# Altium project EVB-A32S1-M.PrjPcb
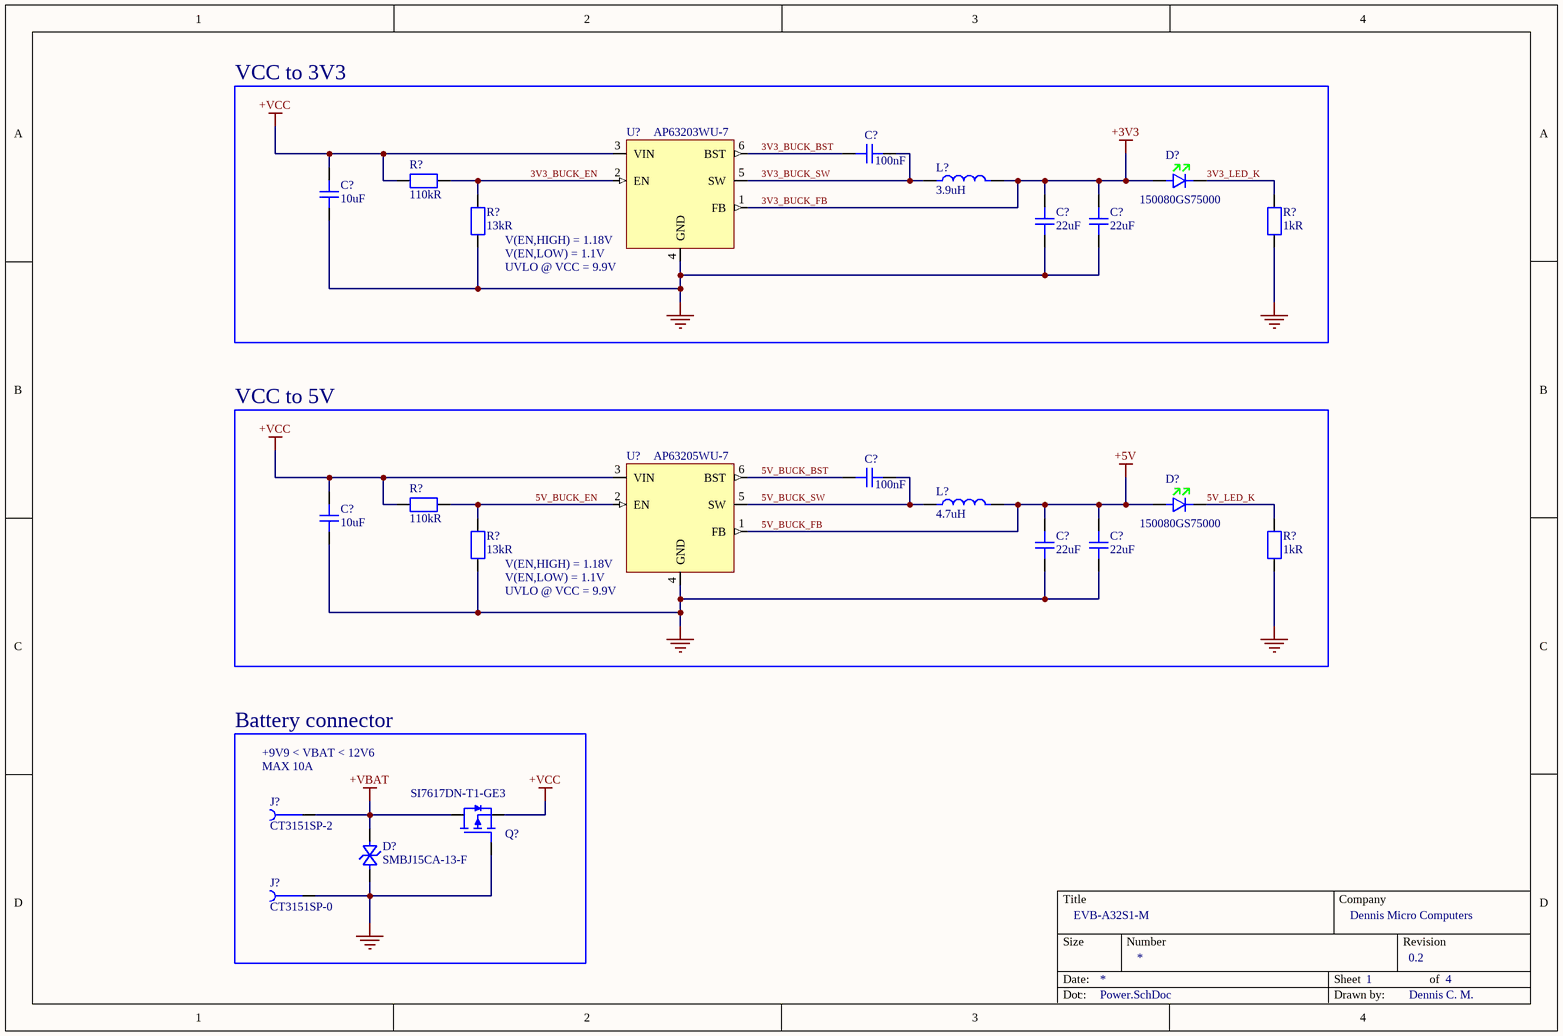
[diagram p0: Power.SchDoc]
Revision: 0.2; Title: EVB-A32S1-M; DrawnBy: Dennis C. M.; CompanyName: Dennis Micro Computers
4 sheets, 88 parts. Net scope: flat (ports and power ports of the same name join across sheets).
Sheets:
  Power.SchDoc
  MCU.SchDoc
  Motor.SchDoc
  Sensing.SchDoc

## Sheet Power.SchDoc: EVB-A32S1-M
size A4; SheetNumber: 1; SheetTotal: 4

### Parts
(Parts that share a designator on the sheet are numbered #1, #2 ... from top to bottom, then left to right.)
C?#1  value 100nF  [C_Yageo_CC_0402_A]  (hidden comment: CC0402MRX5R6BB104)
C?#2  value 10uF  [C_Yageo_CC_0805_A]  (hidden comment: CC0805KRX5R7BB106)
C?#3  value 22uF  [C_Yageo_CC_0805_A]  (hidden comment: CC0805MKX5R6BB226)
C?#4  value 22uF  [C_Yageo_CC_0805_A]  (hidden comment: CC0805MKX5R6BB226)
C?#5  value 100nF  [C_Yageo_CC_0402_A]  (hidden comment: CC0402MRX5R6BB104)
C?#6  value 10uF  [C_Yageo_CC_0805_A]  (hidden comment: CC0805KRX5R7BB106)
C?#7  value 22uF  [C_Yageo_CC_0805_A]  (hidden comment: CC0805MKX5R6BB226)
C?#8  value 22uF  [C_Yageo_CC_0805_A]  (hidden comment: CC0805MKX5R6BB226)
D?#1  150080GS75000  [D_LED_We_150080GS75000]
D?#2  150080GS75000  [D_LED_We_150080GS75000]
D?#3  SMBJ15CA-13-F  [D_TVS_BI_Diodes_SMBJ15CA-13-F_A]
J?#1  CT3151SP-2  [J_CalTest_CT3151SP-2]
J?#2  CT3151SP-0  [J_CalTest_CT3151SP-0]
L?#1  value 3.9uH  [L_Murata_1255AY-XXXX=P3]  (hidden comment: 1255AY-3R9N=P3)
L?#2  value 4.7uH  [L_Murata_1255AY-XXXX=P3]  (hidden comment: 1255AY-4R7M=P3)
Q?#1  SI7617DN-T1-GE3  [Q_Vishay_SI7617DN-T1-GE3]
R?#1  value 110kR  [R_Yageo_RCL_0402_A]  (hidden comment: RC0402FR-07110KL)
R?#2  value 13kR  [R_Yageo_RCL_0402_A]  (hidden comment: RC0402FR-0713KL)
R?#3  value 1kR  [R_Yageo_RCL_0402_A]  (hidden comment: RC0402FR-071KL)
R?#4  value 110kR  [R_Yageo_RCL_0402_A]  (hidden comment: RC0402FR-07110KL)
R?#5  value 13kR  [R_Yageo_RCL_0402_A]  (hidden comment: RC0402FR-0713KL)
R?#6  value 1kR  [R_Yageo_RCL_0402_A]  (hidden comment: RC0402FR-071KL)
U?#1  AP63203WU-7  [U_Diodes_AP623xx]
U?#2  AP63205WU-7  [U_Diodes_AP623xx]

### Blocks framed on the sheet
VCC to 3V3: C?#1-C?#4 D?#1 L?#1 R?#1-R?#3 U?#1
VCC to 5V: C?#5-C?#8 D?#2 L?#2 R?#4-R?#6 U?#2
Battery connector: D?#3 J?#1 J?#2 Q?#1

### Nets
3V3_BUCK_FB: C?#3.2 C?#4.2 D?#1.1 L?#1.2 U?#1.1(FB)  [also labelled +3V3]
5V_BUCK_FB: C?#7.2 C?#8.2 D?#2.1 L?#2.2 U?#2.1(FB)  [also labelled +5V]
+VBAT: D?#3.1 J?#1.1 Q?#1.1(D)
+VCC: C?#2.2 C?#6.2 Q?#1.3(S) R?#1.2 R?#4.2 U?#1.3(VIN) U?#2.3(VIN)
GND: C?#2.1 C?#3.1 C?#4.1 C?#6.1 C?#7.1 C?#8.1 D?#3.2 J?#2.1 Q?#1.2(G) R?#2.1 R?#3.1 R?#5.1 R?#6.1 U?#1.4(GND) U?#2.4(GND)
3V3_BUCK_BST: C?#1.2 U?#1.6(BST)
3V3_BUCK_EN: R?#1.1 R?#2.2 U?#1.2(EN)
3V3_BUCK_SW: C?#1.1 L?#1.1 U?#1.5(SW)
3V3_LED_K: D?#1.2 R?#3.2
5V_BUCK_BST: C?#5.2 U?#2.6(BST)
5V_BUCK_EN: R?#4.1 R?#5.2 U?#2.2(EN)
5V_BUCK_SW: C?#5.1 L?#2.1 U?#2.5(SW)
5V_LED_K: D?#2.2 R?#6.2

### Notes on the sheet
- (near U?#1) V(EN,HIGH) = 1.18V
- V(EN,LOW) = 1.1V
- (near U?#1) UVLO @ VCC = 9.9V
- (near U?#2) V(EN,HIGH) = 1.18V
- (near U?#2) UVLO @ VCC = 9.9V
- +9V9 < VBAT < 12V6
- (near J?#1) MAX 10A

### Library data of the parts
C?#1 C?#5 = CMP-001-00009-8: Multilayer Ceramic Capacitor, 0.1 uF, 25 V, ± 20%, X7R, 0402 [1005 Metric]; Dielectric: X5R; Temperature Coefficient: 30ppm/°C; Voltage Rating: 10V
C?#2 C?#6 = CMP-001-00018-3: 0805 10 uF 16 V ±10% Tolerance X5R Multilayer Ceramic Chip Capacitor; Voltage Rating (DC): 16V
C?#3 C?#4 C?#7 C?#8 = CMP-001-00014-5: Multilayer Ceramic Capacitor, 22 uF, 10 V, ± 20%, X5R, 0805 [2012 Metric]; Voltage Rating (DC): 10V
D?#1 D?#2 = CMP-007-00000-6: WURTH ELEKTRONIK - 150080GS75000 - LED, Green, SMD, 0805, 30 mA, 3.2 V, 520 nm; Forward Current: 30mA; Forward Voltage: 3.2V; Luminous Intensity: 450mcd; Max Reverse Voltage (DC): 5V; Lens Transparency: Clear; Power Dissipation: 105mW; Lens Style: Clear,Flat,Rectangular; Lens Size: 1.25mm; Viewing Angle: 140°; Test Current: 20mA; Dominant Wavelength: 520nm; Lens Color: Colorless
D?#3 = CMP-004-00000-8: Tvs Diode, Bidir, 15V, 600W, Do-214Aa Rohs Compliant: Yes; Max Reverse Leakage Current: 5uA; Reverse Breakdown Voltage: 16.7V; Breakdown Voltage: 19.2V; Clamping Voltage: 24.4V; Power Line Protection: No; Max Surge Current: 24A; Number of Bidirectional Channels: 1; Test Current: 1mA; Value: 280pF; Polarity: Bidirectional; Diode Type: ZENER
J?#1 = CMP-002-00001-9: Conn 4mm Safety Banana Jack F 1 POS Solder RA Thru-Hole 1 Port Bag; pin to pad: 1>1+2+3+4; Body Material: Nylon,Polyamide,PA66; Insulation: Mating End Insulated; Gender: Female
J?#2 = CMP-002-00000-11: Conn 4mm Safety Banana Jack F 1 POS Solder RA Thru-Hole 1 Port Bag; pin to pad: 1>1+2+3+4; Body Material: Nylon,Polyamide,PA66; Insulation: Mating End Insulated; Gender: Female
L?#1 = CMP-006-00002-2: Inductor Power Shielded Wirewound 3.9uH 30% 100KHz Ferrite 4.2A 0.0264Ohm DCR 2424 T/R; DC Resistance (DCR): 26.4mR; Saturation Current: 4.7A
L?#2 = CMP-006-00001-5: Inductor Power Shielded Wirewound 4.7uH 20% 100KHz Ferrite 4A 0.0276Ohm DCR 2424 T/R; DC Resistance (DCR): 27.6mR; Current Rating: 4.5A
Q?#1 = CMP-00000-6: P CHANNEL MOSFET, -30V, 35A; Transistor; Transistor Polarity: P Channel; Continuous Drain Current Id: -35A; Source; pin to pad: 1>5+6+7+8 2>4 3>1+2+3; Rise Time: 43ns; Drain to Source Resistance: 12.3mR; Turn-Off Delay Time: 30ns; Turn-On Delay Time: 40ns; Threshold Voltage: -2.5V; Max Power Dissipation: 52W; Fall Time: 11ns; Power Dissipation: 3.7W; Polarity: P-CHANNEL; Number of Elements: 1; Input Capacitance: 1.8nF; Gate to Source Voltage (Vgs): 25V
R?#1 R?#4 = CMP-009-00000-7: SMD Chip Resistor, 110 kOhm, ± 1%, 63 mW, 0402 [1005 Metric], Thick Film, General Purpose; Max Power Dissipation: 63mW; Voltage Rating (DC): 50V; Temperature Coefficient: 100ppm/°C
R?#2 R?#5 = CMP-009-00001-7: SMD Chip Resistor, 13 kOhm, ± 1%, 63 mW, 0402 [1005 Metric], Thick Film, General Purpose; Temperature Coefficient: 100ppm/°C; Voltage Rating: 50V; Max Power Dissipation: 63mW; Power Rating: 62.5mW
R?#3 R?#6 = CMP-009-00002-7: SMD Chip Resistor, 1 kOhm, ± 1%, 62.5 mW, 0402 [1005 Metric], Thick Film, General Purpose; Temperature Coefficient: 100ppm/°C; Voltage Rating (AC): 50V; Power Rating: 62.5mW; Max Power Dissipation: 63mW
U?#1 = CMP-019-00004-6: AP63203 Series 3.3 V 2 A SMT Fixed Low IQ Synchronous Buck - TSOT-26; Max Duty Cycle: 100%; Output Voltage: 3.3V; Number of Outputs: 1; Max Supply Voltage: 32V; Switching Frequency: 1.1MHz; Min Supply Voltage: 3.8V; Nominal Supply Current: 22uA; Output Current: 2A
U?#2 = CMP-019-00003-6: AP63205 Series 32 V 2 A 1.1 MHz Synchronous Buck Converter -TSOT-26; Number of Outputs: 1; Max Duty Cycle: 100%; Output Current: 2A; Switching Frequency: 1.1MHz; Max Supply Voltage: 32V; Output Voltage: 5V; Nominal Supply Current: 22uA; Min Supply Voltage: 3.8V

## Sheet MCU.SchDoc: EVB-A32S1-M
size A4; SheetNumber: 2; SheetTotal: 4
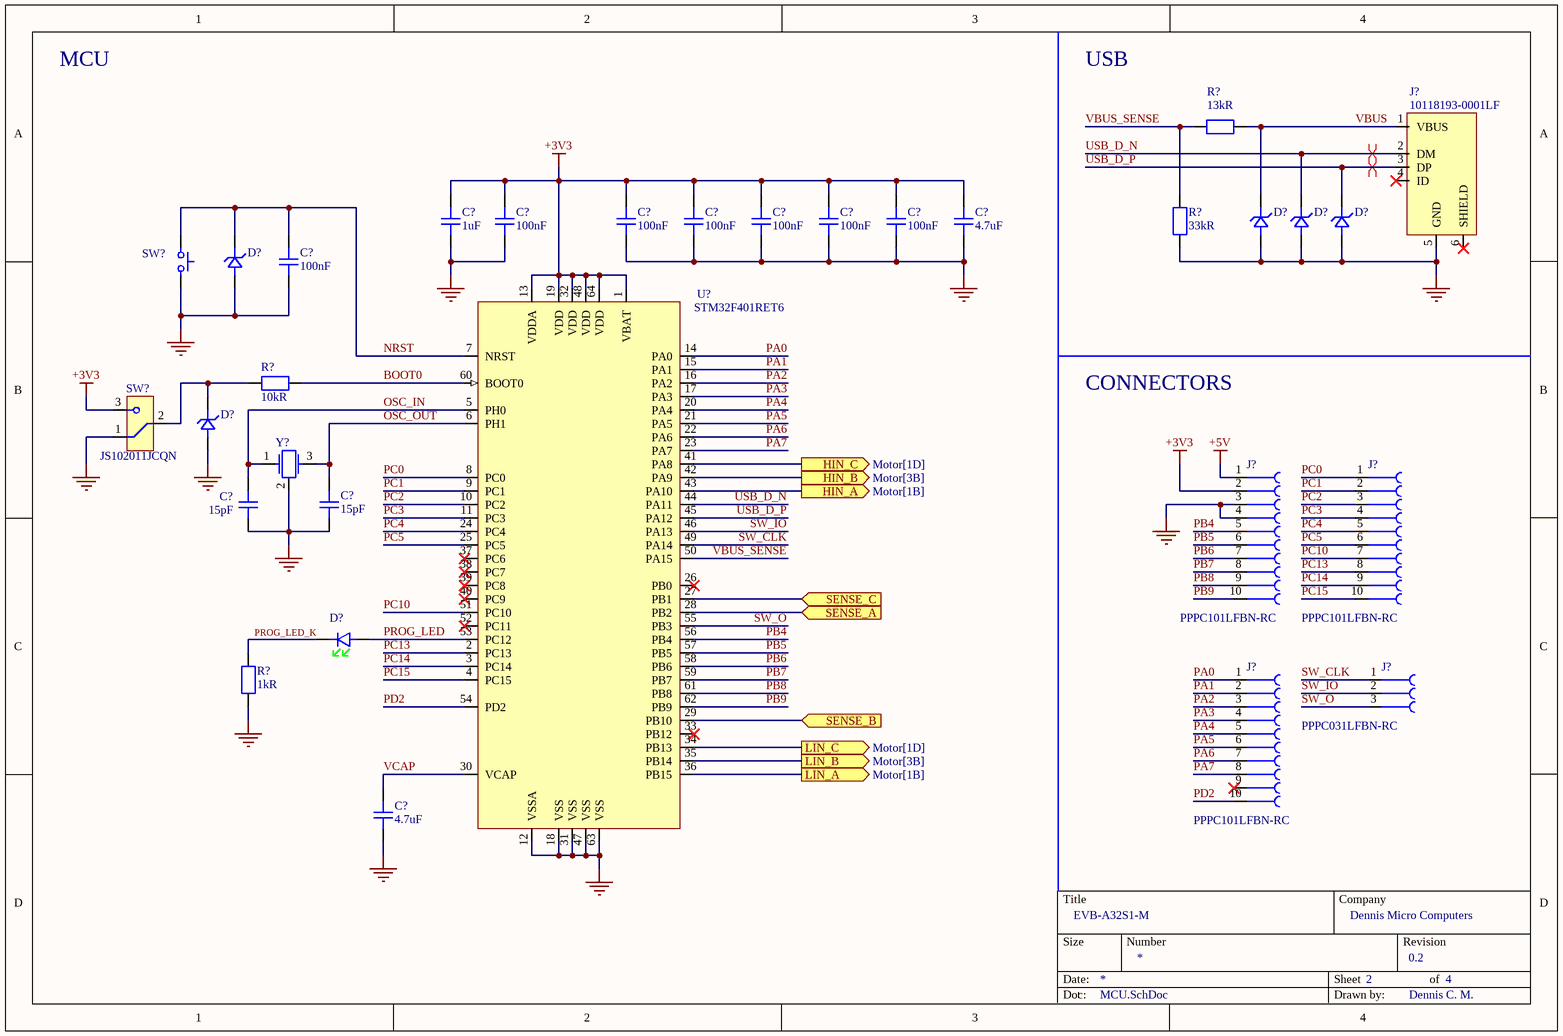
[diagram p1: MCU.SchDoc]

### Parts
(Parts that share a designator on the sheet are numbered #1, #2 ... from top to bottom, then left to right.)
C?#9  value 1uF  [C_Yageo_CC_0603_A]  (hidden comment: CC0603KRX7R7BB105)
C?#10  value 100nF  [C_Yageo_CC_0402_A]  (hidden comment: CC0402MRX5R6BB104)
C?#11  value 100nF  [C_Yageo_CC_0402_A]  (hidden comment: CC0402MRX5R6BB104)
C?#12  value 100nF  [C_Yageo_CC_0402_A]  (hidden comment: CC0402MRX5R6BB104)
C?#13  value 100nF  [C_Yageo_CC_0402_A]  (hidden comment: CC0402MRX5R6BB104)
C?#14  value 100nF  [C_Yageo_CC_0402_A]  (hidden comment: CC0402MRX5R6BB104)
C?#15  value 100nF  [C_Yageo_CC_0402_A]  (hidden comment: CC0402MRX5R6BB104)
C?#16  value 4.7uF  [C_Yageo_CC_0402_A]  (hidden comment: CC0402MRX5R6BB475)
C?#17  value 100nF  [C_Yageo_CC_0402_A]  (hidden comment: CC0402MRX5R6BB104)
C?#18  value 15pF  [C_Yageo_CC_0402_A]  (hidden comment: CC0402JRNPO9BN150)
C?#19  value 15pF  [C_Yageo_CC_0402_A]  (hidden comment: CC0402JRNPO9BN150)
C?#20  value 4.7uF  [C_Yageo_CC_0402_A]  (hidden comment: CC0402MRX5R6BB475)
D?#4  D5V0F1U2S9-7  [D_TVS_Uni_Diodes_SOD-923_B]  (value not drawn)
D?#5  D5V0F1U2S9-7  [D_TVS_Uni_Diodes_SOD-923_B]  (value not drawn)
D?#6  D5V0F1U2S9-7  [D_TVS_Uni_Diodes_SOD-923_B]  (value not drawn)
D?#7  D5V0F1U2S9-7  [D_TVS_Uni_Diodes_SOD-923_B]  (value not drawn)
D?#8  D5V0F1U2S9-7  [D_TVS_Uni_Diodes_SOD-923_B]  (value not drawn)
D?#9  150080GS75000  [D_LED_We_150080GS75000]  (value not drawn)
J?#3  10118193-0001LF  [J_USB_Micro-B_Amphenol_10118193-0001LF]
J?#4  PPPC101LFBN-RC  [J_Sullins_PPPC101LFBN-RC]
J?#5  PPPC101LFBN-RC  [J_Sullins_PPPC101LFBN-RC]
J?#6  PPPC031LFBN-RC  [J_Sullins_01x03_Socket_2.54mm]
J?#7  PPPC101LFBN-RC  [J_Sullins_PPPC101LFBN-RC]
R?#7  value 13kR  [R_Yageo_RCL_0402_A]  (hidden comment: RC0402FR-0713KL)
R?#8  value 33kR  [R_Yageo_RCL_0402_A]  (hidden comment: RC0402FR-0733KL)
R?#9  value 10kR  [R_Yageo_RCL_0402_A]  (hidden comment: RC0402FR-0710KL)
R?#10  value 1kR  [R_Yageo_RCL_0402_A]  (hidden comment: RC0402FR-071KL)
SW?#1  PTS647SN50SMTR2LFS  [SW_Tactitle_SPST_C&K_PTS647SN50SMTR2LFS]  (value not drawn)
SW?#2  JS102011JCQN  [SW_Slide_C&K_JS102011JCQN]
U?#3  STM32F401RET6  [U_STM32F401xD/xE_B]
Y?  ECS-240-12-37B-CKY-TR  [Y_Crystal_GND24_ECS_240-12-37B-CKY-TR]  (value not drawn)

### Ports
HIN_A (out, see Motor[1B]), HIN_B (out, see Motor[3B]), HIN_C (out, see Motor[1D]), LIN_A (out, see Motor[1B]), LIN_B (out, see Motor[3B]), LIN_C (out, see Motor[1D]), SENSE_A (in), SENSE_B (in), SENSE_C (in)

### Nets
+3V3: C?#9.2 C?#10.2 C?#11.2 C?#12.2 C?#13.2 C?#14.2 C?#15.2 C?#16.2 J?#4.2 SW?#2.3 U?#3.1(VBAT) U?#3.13(VDDA) U?#3.19(VDD) U?#3.32(VDD) U?#3.48(VDD) U?#3.64(VDD)  [project net 3V3_BUCK_FB]
+5V: J?#4.1  [project net 5V_BUCK_FB]
GND: C?#9.1 C?#10.1 C?#11.1 C?#12.1 C?#13.1 C?#14.1 C?#15.1 C?#16.1 C?#17.1 C?#18.1 C?#19.1 C?#20.1 D?#4.2 D?#5.2 D?#6.2 D?#7.2 D?#8.2 J?#3.5(GND) J?#4.3 J?#4.4 R?#8.1 R?#10.1 SW?#1.2 SW?#2.1 U?#3.12(VSSA) U?#3.18(VSS) U?#3.31(VSS) U?#3.47(VSS) U?#3.63(VSS) Y?.2
BOOT0: R?#9.2 U?#3.60(BOOT0)
NRST: C?#17.2 D?#7.1 SW?#1.1 U?#3.7(NRST)
OSC_IN: C?#18.2 U?#3.5(PH0) Y?.1
OSC_OUT: C?#19.2 U?#3.6(PH1) Y?.3
PA0: J?#7.1 U?#3.14(PA0)
PA1: J?#7.2 U?#3.15(PA1)
PA2: J?#7.3 U?#3.16(PA2)
PA3: J?#7.4 U?#3.17(PA3)
PA4: J?#7.5 U?#3.20(PA4)
PA5: J?#7.6 U?#3.21(PA5)
PA6: J?#7.7 U?#3.22(PA6)
PA7: J?#7.8 U?#3.23(PA7)
PB4: J?#4.5 U?#3.56(PB4)
PB5: J?#4.6 U?#3.57(PB5)
PB6: J?#4.7 U?#3.58(PB6)
PB7: J?#4.8 U?#3.59(PB7)
PB8: J?#4.9 U?#3.61(PB8)
PB9: J?#4.10 U?#3.62(PB9)
PC0: J?#5.1 U?#3.8(PC0)
PC1: J?#5.2 U?#3.9(PC1)
PC2: J?#5.3 U?#3.10(PC2)
PC3: J?#5.4 U?#3.11(PC3)
PC4: J?#5.5 U?#3.24(PC4)
PC5: J?#5.6 U?#3.25(PC5)
PC10: J?#5.7 U?#3.51(PC10)
PC13: J?#5.8 U?#3.2(PC13)
PC14: J?#5.9 U?#3.3(PC14)
PC15: J?#5.10 U?#3.4(PC15)
PD2: J?#7.10 U?#3.54(PD2)
PROG_LED: D?#9.1 U?#3.53(PC12)
PROG_LED_K: D?#9.2 R?#10.2
SW_CLK: J?#6.1 U?#3.49(PA14)
SW_IO: J?#6.2 U?#3.46(PA13)
SW_O: J?#6.3 U?#3.55(PB3)
USB_D_N: D?#5.1 J?#3.2(DM) U?#3.44(PA11)
USB_D_P: D?#6.1 J?#3.3(DP) U?#3.45(PA12)
VBUS: D?#4.1 J?#3.1(VBUS) R?#7.2
VBUS_SENSE: R?#7.1 R?#8.2 U?#3.50(PA15)
VCAP: C?#20.2 U?#3.30(VCAP)
NetD?#8_1: D?#8.1 R?#9.1 SW?#2.2
NetU?#3_27: U?#3.27(PB1) ; port SENSE_C
NetU?#3_28: U?#3.28(PB2) ; port SENSE_A
NetU?#3_29: U?#3.29(PB10) ; port SENSE_B
NetU?#3_34: U?#3.34(PB13) ; port LIN_C
NetU?#3_35: U?#3.35(PB14) ; port LIN_B
NetU?#3_36: U?#3.36(PB15) ; port LIN_A
NetU?#3_41: U?#3.41(PA8) ; port HIN_C
NetU?#3_42: U?#3.42(PA9) ; port HIN_B
NetU?#3_43: U?#3.43(PA10) ; port HIN_A

Not connected (* = marked no-connect by the designer): J?#3 4(ID)* 6(SHIELD)*; J?#7 9*; U?#3 26(PB0)* 33(PB12)* 37(PC6)* 38(PC7)* 39(PC8)* 40(PC9)* 52(PC11)*

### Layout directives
differential pair; differential pair class USB: USB_D_N, USB_D_P

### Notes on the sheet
- MCU
- USB
- CONNECTORS

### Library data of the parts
C?#9 = CMP-001-00019-1: Multilayer Ceramic Capacitor, 1 uF, 16 V, ± 10%, X7R, 0603 [1608 Metric]; Voltage: 16V; Dissipation Factor: 5%
C?#10-C?#15 C?#17 = CMP-001-00009-8: as C?#1 on sheet Power
C?#16 C?#20 = CMP-001-00015-8: Multilayer Ceramic Capacitor, 4.7 uF, 50 V, ± 10%, X5R, 0402 [1005 Metric]; Tolerance: 20%; Temperature Coefficient: 30ppm/°C; Voltage Rating (DC): 10V
C?#18 C?#19 = CMP-001-00017-9: Multilayer Ceramic Capacitor, 15 pF, 10 V, ± 5%, X7R, 0402 [1005 Metric]; Insulation Resistance: 100GR; Dielectric: C0G; Voltage Rating (DC): 50V; Temperature Coefficient: 30ppm/°C
D?#4-D?#8 = CMP-004-00003-1: Diode TVS Dual Uni-Dir 5.5V 250000W 2-Pin SOD-923 T/R; Max Power Dissipation: 250mW; ESD Protection: Yes; Max Reverse Leakage Current: 100nA; Capacitance: 0.5pF @ 1MHz; Max Surge Current: 1.5A; Diode Type: ZENER; Direction: Unidirectional; Breakdown Voltage: 6V; Clamping Voltage: 10V; Value: 5E-13F; Peak Pulse Power: 250kW; Number of Unidirectional Channels: 1
D?#9 = CMP-007-00000-6: WURTH ELEKTRONIK - 150080GS75000 - LED, Green, SMD, 0805, 30 mA, 3.2 V, 520 nm; Viewing Angle: 140°; Lens Transparency: Clear; Reverse Voltage: 5V; Lens Size: 1.25mm; Lens Color: Colorless; Lens Style: Clear,Flat,Rectangular; Power Dissipation: 105mW; Wavelength: 520nm; Forward Voltage: 3.2V; Test Current: 20mA; Forward Current: 30mA; Luminous Intensity: 450mcd
J?#3 = CMP-002-00002-7: Usb Connector, 5 Contact(S), Female, Right Angle, Surface Mount Terminal, Locking, Receptacle; Number of Contacts: 5; Current Rating: 1.8A; Connector Type: USB,Receptacle; Pitch: 650um; Number of Ports: 1; Voltage Rating: 100V; USB Standard: USB 2.0; Insulation Resistance: 1GR
J?#4 J?#5 J?#7 = CMP-002-00003-1: 10 Position Total Single Row 2.54 mm Pitch Straight Female Header; Voltage Rating: 250V; Number of Contacts: 10; Pitch: 0.1inch; Current Rating: 3A
J?#6 = CMP-002-00004-1: 3 Position Total Single Row 2.54 mm Pitch Straight Female Header; Voltage Rating: 250V; Number of Positions: 3; Pitch: 2.54mm
R?#7 = CMP-009-00001-7: SMD Chip Resistor, 13 kOhm, ± 1%, 63 mW, 0402 [1005 Metric], Thick Film, General Purpose; Voltage Rating (DC): 50V; Temperature Coefficient: 100ppm/°C; Max Power Dissipation: 63mW; Power Rating: 62.5mW
R?#8 = CMP-009-00005-8: SMD Chip Resistor, 33 kOhm, ± 1%, 63 mW, 0402 [1005 Metric], Thick Film, General Purpose; Power Rating: 63mW; Temperature Coefficient: 100ppm/°C; Voltage Rating (AC): 50V
R?#9 = CMP-009-00003-7: SMD Chip Resistor, 10 kOhm, ± 1%, 62.5 mW, 0402 [1005 Metric], Thick Film, General Purpose; Power Rating: 62.5mW; Max Power Dissipation: 63mW; Temperature Coefficient: 100ppm/°C; Voltage Rating (DC): 50V
R?#10 = CMP-009-00002-7: SMD Chip Resistor, 1 kOhm, ± 1%, 62.5 mW, 0402 [1005 Metric], Thick Film, General Purpose; Temperature Coefficient: 100ppm/°C; Max Power Dissipation: 63mW; Voltage Rating (AC): 50V; Power Rating: 62.5mW
SW?#1 = CMP-011-00000-10: Switch Tactile N.O. SPST Round Button Gull Wing 0.05A 12VDC 100000Cycles 0.98N SMD T/R; pin to pad: 1>1+2 2>3+4; Ratings: IP40; Switch Function: Off-Mom; Illumination Type: Non-Illuminated; Actuator Type: Standard; Number of Positions: 2; Operating Force: 100gf; Switch Travel: 0.25mm
SW?#2 = CMP-011-00001-7: JS Series Sub-Miniature Slide Switch SPDT On-On Top Slide 0.3A 6VDC J-Lead Surface Mount T/R; Voltage Rating (DC): 6V; Switch Travel: 2mm; Actuator Material: Nylon,Polyamide,PA46; Electrical Life: 5000Cycles; Actuator Type: Standard
U?#3 = CMP-020-00000-6: MCU 32-bit STM32 ARM Cortex M4 RISC 512KB Flash 1.8V/2.5V/3.3V 64-Pin LQFP Tray; Operating Supply Voltage: 3.3V; Peripherals: Brown-out Detect/Reset,POR,PWM,WDT,DMA; Nominal Supply Current: 1.8uA; Number of ADC Channels: 12; Interface: I2C,SPI,USB,IrDA,SDIO,UART,USART,LIN,I2S; Clock Frequency: 84MHz; Number of USB Channels: 1; Number of Timers/Counters: 8; Number of Channels: 16; Number of PWM Channels: 23; Number of UART Channels: 3; Number of Programmable I/O: 50; Watchdog Timer: Yes; Max Power Dissipation: 313mW; Min Supply Voltage: 1.7V; Data Bus Width: 32b; RAM Size: 96KB; Max Supply Voltage: 3.6V; Oscillator Type: Internal
Y? = CMP-003-00000-4: Crystal 24MHz ±10ppm (Tol) ±10ppm (Stability) 12pF FUND 50Ohm 4-Pin Mini-CSMD T/R; pin to pad: 2>2+4

## Sheet Motor.SchDoc: EVB-A32S1-M
size A4; SheetNumber: 3; SheetTotal: 4
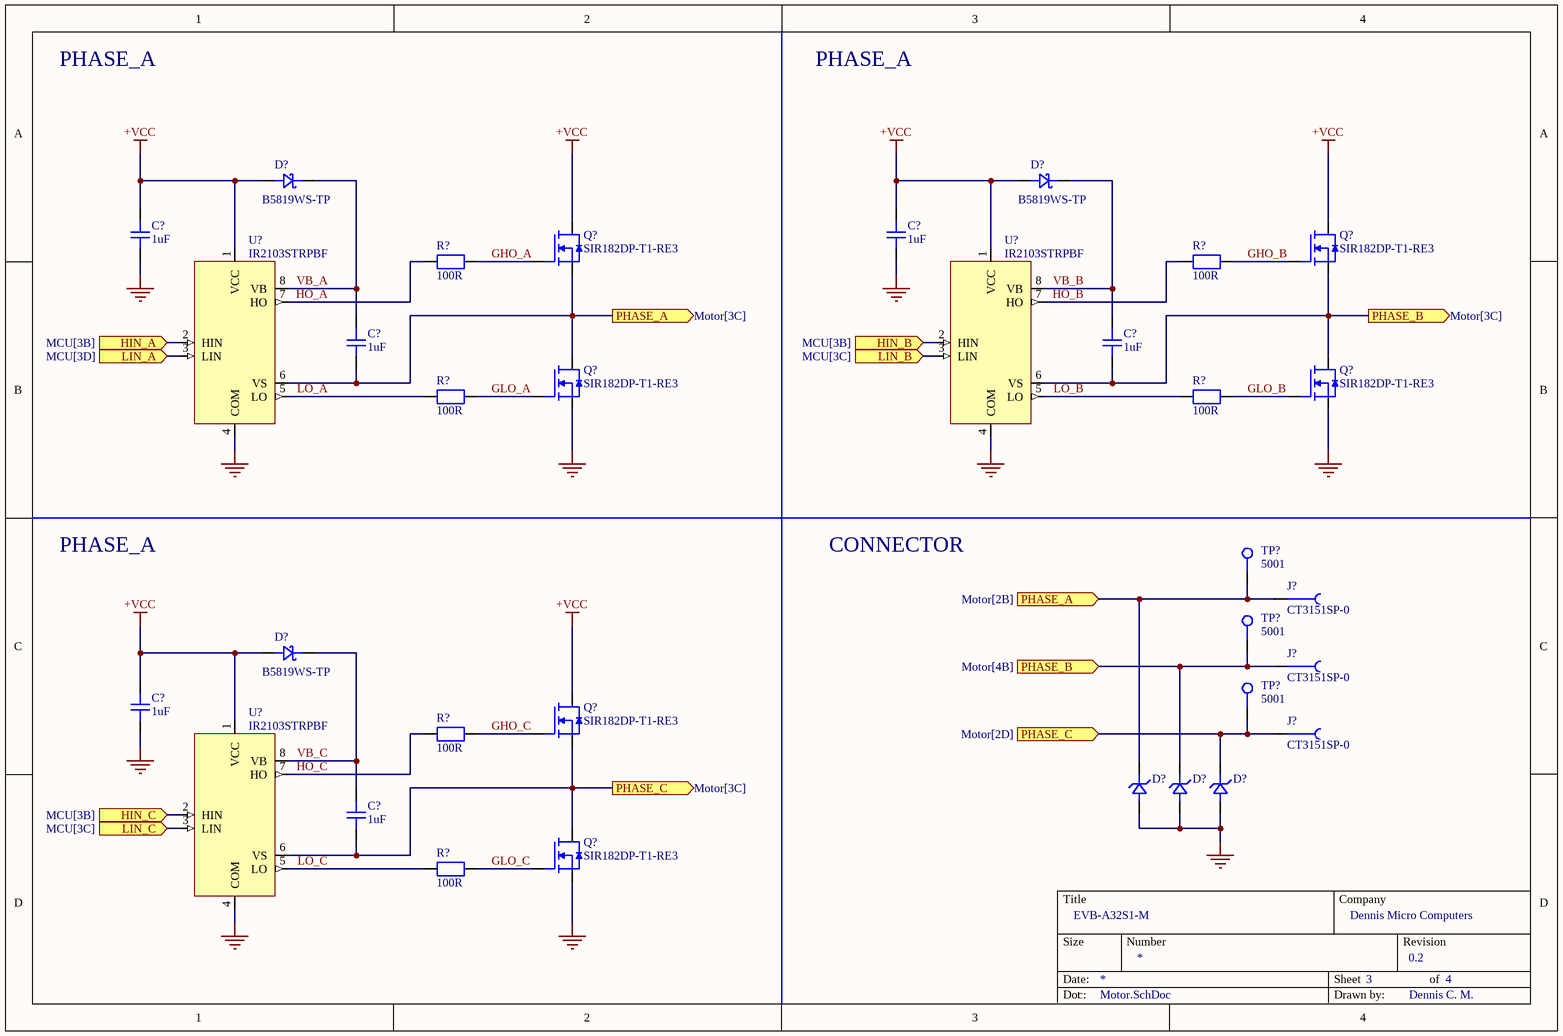
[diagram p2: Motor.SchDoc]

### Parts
(Parts that share a designator on the sheet are numbered #1, #2 ... from top to bottom, then left to right.)
C?#21  value 1uF  [C_Yageo_CC_0603_A]  (hidden comment: CC0603KRX7R7BB105)
C?#22  value 1uF  [C_Yageo_CC_0603_A]  (hidden comment: CC0603KRX7R7BB105)
C?#23  value 1uF  [C_Yageo_CC_0603_A]  (hidden comment: CC0603KRX7R7BB105)
C?#24  value 1uF  [C_Yageo_CC_0603_A]  (hidden comment: CC0603KRX7R7BB105)
C?#25  value 1uF  [C_Yageo_CC_0603_A]  (hidden comment: CC0603KRX7R7BB105)
C?#26  value 1uF  [C_Yageo_CC_0603_A]  (hidden comment: CC0603KRX7R7BB105)
D?#10  B5819WS-TP  [D_Schottky_Micro_SOD-323]
D?#11  B5819WS-TP  [D_Schottky_Micro_SOD-323]
D?#12  B5819WS-TP  [D_Schottky_Micro_SOD-323]
D?#13  D5V0F1U2S9-7  [D_TVS_Uni_Diodes_SOD-923_B]  (value not drawn)
D?#14  D5V0F1U2S9-7  [D_TVS_Uni_Diodes_SOD-923_B]  (value not drawn)
D?#15  D5V0F1U2S9-7  [D_TVS_Uni_Diodes_SOD-923_B]  (value not drawn)
J?#8  CT3151SP-0  [J_CalTest_CT3151SP-0]
J?#9  CT3151SP-0  [J_CalTest_CT3151SP-0]
J?#10  CT3151SP-0  [J_CalTest_CT3151SP-0]
Q?#2  SIR182DP-T1-RE3  [Q_Vishay_PowerPACK-SO-8-Single]
Q?#3  SIR182DP-T1-RE3  [Q_Vishay_PowerPACK-SO-8-Single]
Q?#4  SIR182DP-T1-RE3  [Q_Vishay_PowerPACK-SO-8-Single]
Q?#5  SIR182DP-T1-RE3  [Q_Vishay_PowerPACK-SO-8-Single]
Q?#6  SIR182DP-T1-RE3  [Q_Vishay_PowerPACK-SO-8-Single]
Q?#7  SIR182DP-T1-RE3  [Q_Vishay_PowerPACK-SO-8-Single]
R?#11  value 100R  [R_Yageo_RCL_1206_A]  (hidden comment: RC1206FR-07100RL)
R?#12  value 100R  [R_Yageo_RCL_1206_A]  (hidden comment: RC1206FR-07100RL)
R?#13  value 100R  [R_Yageo_RCL_1206_A]  (hidden comment: RC1206FR-07100RL)
R?#14  value 100R  [R_Yageo_RCL_1206_A]  (hidden comment: RC1206FR-07100RL)
R?#15  value 100R  [R_Yageo_RCL_1206_A]  (hidden comment: RC1206FR-07100RL)
R?#16  value 100R  [R_Yageo_RCL_1206_A]  (hidden comment: RC1206FR-07100RL)
TP?#1  5001  [TP_Keystone_TH]
TP?#2  5001  [TP_Keystone_TH]
TP?#3  5001  [TP_Keystone_TH]
U?#4  IR2103STRPBF  [U_Infineon_8-SOIC_3.9mm]
U?#5  IR2103STRPBF  [U_Infineon_8-SOIC_3.9mm]
U?#6  IR2103STRPBF  [U_Infineon_8-SOIC_3.9mm]

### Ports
HIN_A (in, see MCU[3B]), HIN_B (in, see MCU[3B]), HIN_C (in, see MCU[3B]), LIN_A (in, see MCU[3D]), LIN_B (in, see MCU[3C]), LIN_C (in, see MCU[3C]), PHASE_A (in, see Motor[2B]), PHASE_A (out, see Motor[3C]), PHASE_B (in, see Motor[4B]), PHASE_B (out, see Motor[3C]), PHASE_C (in, see Motor[2D]), PHASE_C (out, see Motor[3C])

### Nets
+VCC: C?#21.2 C?#22.2 C?#25.2 D?#10.2 D?#11.2 D?#12.2 Q?#2.1(D) Q?#3.1(D) Q?#6.1(D) U?#4.1(VCC) U?#5.1(VCC) U?#6.1(VCC)
GND: C?#21.1 C?#22.1 C?#25.1 D?#13.2 D?#14.2 D?#15.2 Q?#4.3(S) Q?#5.3(S) Q?#7.3(S) U?#4.4(COM) U?#5.4(COM) U?#6.4(COM)
GHO_A: Q?#2.2(G) R?#11.2
GHO_B: Q?#3.2(G) R?#12.2
GHO_C: Q?#6.2(G) R?#15.2
GLO_A: Q?#4.2(G) R?#13.2
GLO_B: Q?#5.2(G) R?#14.2
GLO_C: Q?#7.2(G) R?#16.2
HO_A: R?#11.1 U?#4.7(HO)
HO_B: R?#12.1 U?#5.7(HO)
HO_C: R?#15.1 U?#6.7(HO)
LO_A: R?#13.1 U?#4.5(LO)
LO_B: R?#14.1 U?#5.5(LO)
LO_C: R?#16.1 U?#6.5(LO)
VB_A: C?#23.2 D?#10.1 U?#4.8(VB)
VB_B: C?#24.2 D?#11.1 U?#5.8(VB)
VB_C: C?#26.2 D?#12.1 U?#6.8(VB)
NetC?#23_1: C?#23.1 D?#13.1 J?#8.1 Q?#2.3(S) Q?#4.1(D) TP?#1.1 U?#4.6(VS) ; port PHASE_A
NetC?#24_1: C?#24.1 D?#14.1 J?#9.1 Q?#3.3(S) Q?#5.1(D) TP?#2.1 U?#5.6(VS) ; port PHASE_B
NetC?#26_1: C?#26.1 D?#15.1 J?#10.1 Q?#6.3(S) Q?#7.1(D) TP?#3.1 U?#6.6(VS) ; port PHASE_C
NetU?#3_34: U?#6.3(LIN) ; port LIN_C
NetU?#3_35: U?#5.3(LIN) ; port LIN_B
NetU?#3_36: U?#4.3(LIN) ; port LIN_A
NetU?#3_41: U?#6.2(HIN) ; port HIN_C
NetU?#3_42: U?#5.2(HIN) ; port HIN_B
NetU?#3_43: U?#4.2(HIN) ; port HIN_A

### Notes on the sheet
- PHASE_A
- CONNECTOR

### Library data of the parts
C?#21-C?#26 = CMP-001-00019-1: as C?#9 on sheet MCU
D?#10-D?#12 = CMP-004-00004-1: Rectifier Diode, Schottky, 1 Phase, 1 Element, 1A, 40V V(RRM), Silicon; Peak Non-Repetitive Surge Current: 10A; Value: 48pF; Max Reverse Leakage Current: 1mA; Forward Voltage: 900mV; Max Reverse Current: 7uA
D?#13-D?#15 = CMP-004-00003-1: as D?#4 on sheet MCU
J?#8-J?#10 = CMP-002-00000-11: Conn 4mm Safety Banana Jack F 1 POS Solder RA Thru-Hole 1 Port Bag; pin to pad: 1>1+2+3+4; Gender: Female; Insulation: Mating End Insulated; Body Material: Nylon,Polyamide,PA66
Q?#2-Q?#7 = CMP-013-00000-2: TrenchFET Gen IV Power MOSFET N-Channel Single 60V VDS ±20V VGS 60A ID 8-Pin PowerPAK SOIC T/R; pin to pad: 1>5 2>4 3>1+2+3; Rds On Max: 2.8mR; Max Power Dissipation: 69.4W; Input Capacitance: 3.25nF
R?#11-R?#16 = CMP-009-00004-8: SMD Chip Resistor, 100 Ohm, ± 1%, 250 mW, 1206 [3216 Metric], Thick Film, General Purpose; Max Power Dissipation: 250mW; Voltage Rating (AC): 200V; Temperature Coefficient: 100ppm/°C
TP?#1-TP?#3 = CMP-000000-1: TEST POINT, PCB, THROUGH HOLE; Product R; Range: -; Connector Colour: Black; Mounting: Through Hole; Body Material: Bronze; Insulation: Insulated; Plating: Silver; Number of Ports: 1; Inside Diameter: 1.27mm; Hole Diameter: 1.6mm; Outside Diameter: 2.54mm
U?#4-U?#6 = CMP-024-00000-2: 600 V half-bridge gate driver IC with shoot through protection, SOIC 8N, RoHS; Number of Outputs: 2; Max Supply Voltage: 20V; Propagation Delay: 680ns; Fall Time: 60ns; Channel Type: Independent; Output Current: 360mA

## Sheet Sensing.SchDoc: EVB-A32S1-M
size A4; Author: Dennis C. M; CompanyName: Dennis Micro Computers; DrawnBy: Dennis C. M.; SheetNumber: 4; SheetTotal: 4; Size: A4

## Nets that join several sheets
3V3_BUCK_FB: Power (5 pins), MCU (16 pins)
5V_BUCK_FB: Power (5 pins), MCU (J?#4.1)
+VCC: Power (7 pins), Motor (12 pins)
GND: Power (15 pins), MCU (30 pins), Motor (12 pins)
NetU?#3_34: MCU (U?#3.34), Motor (U?#6.3)
NetU?#3_35: MCU (U?#3.35), Motor (U?#5.3)
NetU?#3_36: MCU (U?#3.36), Motor (U?#4.3)
NetU?#3_41: MCU (U?#3.41), Motor (U?#6.2)
NetU?#3_42: MCU (U?#3.42), Motor (U?#5.2)
NetU?#3_43: MCU (U?#3.43), Motor (U?#4.2)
